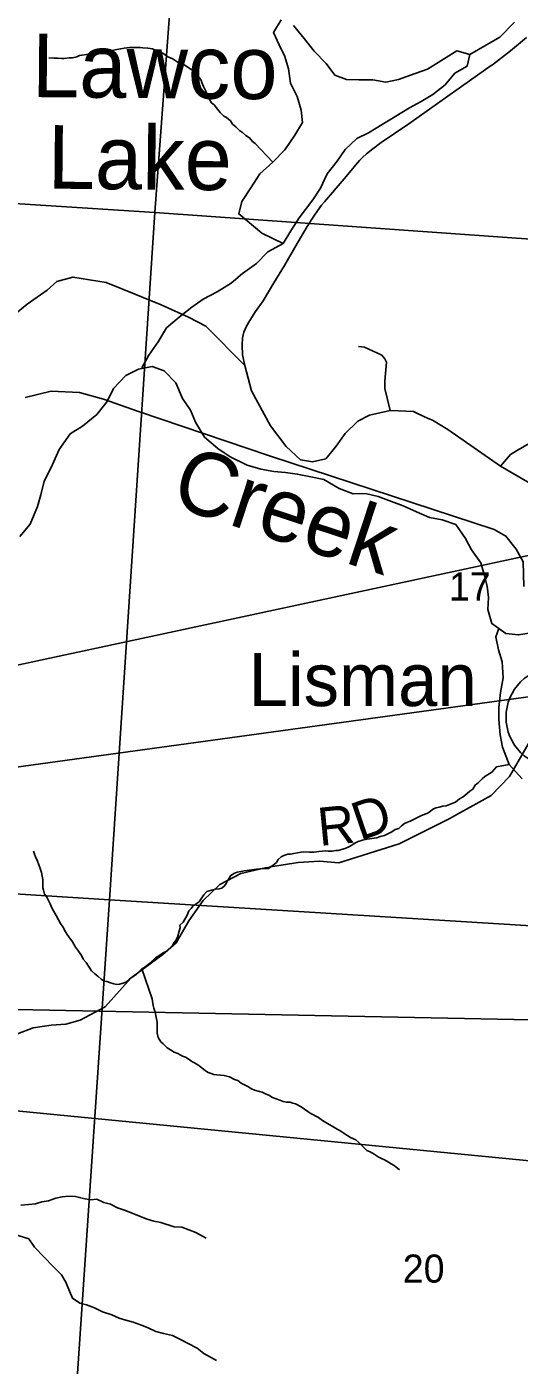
# Model space of a CAD drawing. Extents: x 0 to 44, y -23.8 to 22.
# Drawn here: x 7.321 to 8.055, y 16.706 to 18.701 of the extents above; entities that cross this region are included whole.
import ezdxf

# ---------------------------------------------------------------- set-up
doc = ezdxf.new("R2010")
doc.units = 0
for name, color, linetype in [('GM_X_County_Road', 7, 'Continuous'), ('GM_X_County_Road_Text', 7, 'Continuous'), ('GM_X_Minor_Lake', 7, 'Continuous'), ('GM_X_Minor_Lake_Text', 7, 'Continuous'), ('GM_X_Minor_River', 7, 'Continuous'), ('GM_X_Minor_River_Text', 7, 'Continuous'), ('GM_X_Rail_Line', 7, 'Continuous'), ('GM_X_Section', 7, 'Continuous'), ('GM_X_Section_Text', 7, 'Continuous'), ('GM_X_State_Route', 7, 'Continuous'), ('GM_X_Township_Road', 7, 'Continuous'), ('GM_X_Unincorporated', 7, 'Continuous'), ('GM_X_Unincorporated_Text', 7, 'Continuous'), ('SH_Data', 7, 'Continuous')]:
    doc.layers.add(name, color=color, linetype=linetype)

msp = doc.modelspace()

# ---------------------------------------------------------------- linework, layer by layer
at = {"layer": 'GM_X_County_Road'}
for points in [[(6.9605, 18.0572), (6.9631, 18.0586), (7.0676, 18.0977), (7.1245, 18.1197), (7.1631, 18.1368), (7.1965, 18.1482), (7.2162, 18.1554), (7.226, 18.1596), (7.2355, 18.1759), (7.2488, 18.2089), (7.2601, 18.2305), (7.2791, 18.2525), (7.3219, 18.2874), (7.3518, 18.3079), (7.3662, 18.3212), (7.3901, 18.3277), (7.4398, 18.3193), (7.4838, 18.3016), (7.5032, 18.2938)], [(7.5032, 18.2938), (7.5216, 18.2864), (7.5625, 18.2681), (7.5883, 18.2545), (7.6465, 18.1961)], [(8.0274, 18.0459), (8.0425, 18.0631), (8.0562, 18.0718), (8.0828, 18.0867)], [(7.6845, 17.4488), (7.726, 17.4555), (7.7575, 17.4574), (7.7866, 17.4551), (7.8764, 17.4832), (7.95, 17.5201), (8.0136, 17.5554), (8.0409, 17.5834), (8.0981, 17.6821), (8.1073, 17.6872)], [(7.3076, 17.2002), (7.3307, 17.2091), (7.3578, 17.213), (7.3795, 17.2145), (7.4012, 17.2204), (7.438, 17.2403), (7.477, 17.2835), (7.524, 17.3181), (7.5441, 17.3355), (7.5631, 17.3686), (7.5843, 17.3985), (7.6089, 17.4224), (7.6404, 17.4388), (7.6767, 17.4475), (7.6807, 17.4481), (7.6845, 17.4488)]]:
    msp.add_lwpolyline(points, dxfattribs=at)
at = {"layer": 'GM_X_Minor_Lake'}
for points in [[(7.7007, 18.7107), (7.6893, 18.6918), (7.6975, 18.6736), (7.7058, 18.6561), (7.7117, 18.6378), (7.7146, 18.6165), (7.7244, 18.5968), (7.7304, 18.5762), (7.7325, 18.558), (7.7211, 18.5391), (7.7058, 18.5171), (7.6883, 18.499), (7.6685, 18.4816), (7.6555, 18.4604), (7.6418, 18.44), (7.6372, 18.4218), (7.6719, 18.393), (7.7036, 18.3775)], [(7.8309, 18.5424), (7.8917, 18.58), (7.9092, 18.5891), (7.9267, 18.5996), (7.9449, 18.614), (7.9594, 18.6313), (7.9776, 18.6419), (7.9815, 18.6593), (7.9626, 18.6647), (7.9185, 18.6376), (7.9003, 18.6309), (7.8753, 18.6219), (7.8563, 18.6182), (7.8374, 18.6213), (7.8162, 18.6214), (7.798, 18.6222), (7.7806, 18.6284), (7.7678, 18.6459), (7.7497, 18.6642), (7.7347, 18.6832), (7.7189, 18.7023)], [(7.7036, 18.3775), (7.7151, 18.3964), (7.7273, 18.4161), (7.7479, 18.4425), (7.7593, 18.46), (7.7693, 18.4812), (7.7838, 18.5001), (7.796, 18.5175), (7.8135, 18.5341), (7.8309, 18.5424)]]:
    msp.add_lwpolyline(points, dxfattribs=at)
at = {"layer": 'GM_X_Minor_River'}
for points in [[(8.0484, 18.7072), (8.0263, 18.6853), (7.9815, 18.6593)], [(7.6883, 18.499), (7.6617, 18.5267), (7.658, 18.5294), (7.6535, 18.5352), (7.6478, 18.5387), (7.6426, 18.5433), (7.6388, 18.5456), (7.6332, 18.5514), (7.6279, 18.5556), (7.6249, 18.5602), (7.6193, 18.5656), (7.6152, 18.5676), (7.6095, 18.573), (7.6058, 18.5776), (7.6006, 18.5841), (7.5968, 18.5872), (7.5931, 18.5933), (7.5909, 18.599), (7.5883, 18.6048), (7.5846, 18.6117), (7.5824, 18.6174), (7.5813, 18.6212), (7.5768, 18.627), (7.5745, 18.6308), (7.5693, 18.635), (7.5633, 18.6389), (7.5542, 18.6451), (7.547, 18.6475), (7.538, 18.6533), (7.5316, 18.656), (7.5241, 18.6614), (7.5176, 18.6638), (7.5086, 18.6677), (7.5018, 18.6686), (7.4946, 18.6694), (7.4904, 18.6698), (7.4866, 18.6699), (7.4801, 18.6696), (7.4748, 18.6697), (7.4706, 18.669), (7.4665, 18.6686), (7.4615, 18.6679), (7.4558, 18.6669), (7.4486, 18.665), (7.4433, 18.664), (7.4361, 18.6629), (7.4319, 18.6622), (7.4212, 18.6608), (7.4159, 18.6598), (7.4106, 18.6594), (7.4038, 18.6584), (7.3999, 18.6577), (7.3958, 18.6558), (7.3893, 18.6544), (7.3847, 18.6541), (7.3771, 18.6534), (7.373, 18.6535), (7.3677, 18.6539), (7.3616, 18.654), (7.3544, 18.6545)], [(7.7036, 18.3775), (7.6809, 18.3651), (7.6637, 18.3477), (7.6431, 18.333), (7.626, 18.3187), (7.6054, 18.3058), (7.5845, 18.2946), (7.5673, 18.2829), (7.5487, 18.2678), (7.5296, 18.2519), (7.5173, 18.2311), (7.5035, 18.2111), (7.4935, 18.1936), (7.4931, 18.1916)], [(8.0075, 17.8671), (8.0031, 17.8843), (7.9979, 17.9018), (7.9844, 17.9212), (7.9754, 17.9383), (7.9607, 17.9589), (7.9407, 17.9658), (7.9217, 17.9693), (7.9021, 17.9778), (7.8824, 17.987), (7.865, 17.9932), (7.8449, 18.0009), (7.8264, 18.0051), (7.8078, 18.0049), (7.787, 18.0126), (7.764, 18.026), (7.7446, 18.0302), (7.7246, 18.0341), (7.7071, 18.0365), (7.6897, 18.0377), (7.6704, 18.0412), (7.65, 18.0474), (7.6246, 18.0597), (7.6061, 18.0723), (7.5865, 18.0891), (7.573, 18.1116), (7.5652, 18.1291), (7.5535, 18.1466), (7.5434, 18.1702), (7.5261, 18.1878), (7.5083, 18.1943), (7.4878, 18.1906), (7.4688, 18.1812), (7.4505, 18.1616), (7.4413, 18.1423), (7.4256, 18.123), (7.4046, 18.1056), (7.3859, 18.0939), (7.3695, 18.0705), (7.3575, 18.044), (7.3472, 18.0235), (7.3421, 18.003), (7.3374, 17.986), (7.3263, 17.9595), (7.311, 17.9413)], [(8.073, 17.7977), (8.0544, 17.7944), (8.0355, 17.7964), (8.0147, 17.8113), (8.0088, 17.8322), (8.0097, 17.8501), (8.0075, 17.8671)], [(8.0598, 17.5798), (8.0406, 17.6016), (8.0305, 17.6271), (8.0269, 17.6457), (8.0248, 17.6685), (8.0249, 17.6863), (8.0273, 17.7087), (8.0316, 17.7307), (8.0299, 17.7543), (8.0247, 17.7721), (8.0207, 17.7915), (8.0249, 17.804)], [(8.0406, 17.6016), (8.0213, 17.5978), (8.0144, 17.5899), (8.0041, 17.5836), (7.9999, 17.5802), (7.9945, 17.5746), (7.9899, 17.5708), (7.986, 17.5648), (7.9818, 17.5618), (7.978, 17.5581), (7.9719, 17.5532), (7.9665, 17.5502), (7.9604, 17.5454), (7.9539, 17.5428), (7.9463, 17.5399), (7.9417, 17.5392), (7.936, 17.5377), (7.9314, 17.537), (7.9276, 17.5352), (7.9192, 17.5288), (7.9146, 17.5273), (7.9089, 17.5248), (7.9009, 17.5211), (7.8937, 17.5173), (7.8845, 17.5133), (7.8799, 17.5099), (7.8757, 17.5062), (7.8704, 17.5047), (7.8654, 17.501), (7.8547, 17.4958), (7.8479, 17.494), (7.8433, 17.4921), (7.8391, 17.4918), (7.8323, 17.4908), (7.8281, 17.49), (7.822, 17.4886), (7.8155, 17.4868), (7.8113, 17.4846), (7.8022, 17.4794), (7.7961, 17.4764), (7.7904, 17.4749), (7.7854, 17.4731), (7.7816, 17.4732), (7.7767, 17.4725), (7.7706, 17.4725), (7.7664, 17.4726), (7.7565, 17.4716), (7.7497, 17.4709), (7.7429, 17.471), (7.7345, 17.4715), (7.7304, 17.4708), (7.7247, 17.4697), (7.7193, 17.469), (7.7144, 17.4679), (7.7106, 17.4676), (7.7045, 17.4658), (7.7003, 17.4639), (7.6961, 17.4598), (7.6934, 17.4556), (7.6888, 17.4515), (7.6819, 17.4463), (7.6766, 17.4463), (7.6686, 17.4461), (7.6637, 17.4454), (7.6568, 17.4443), (7.6527, 17.444), (7.6454, 17.4429), (7.6405, 17.4419), (7.6352, 17.4408), (7.6302, 17.4389), (7.6249, 17.4356), (7.6229, 17.4318), (7.6206, 17.4281), (7.6187, 17.4243), (7.6163, 17.4205), (7.6121, 17.4171), (7.6083, 17.416), (7.6026, 17.4154), (7.5969, 17.4139), (7.5897, 17.4121), (7.5855, 17.4072), (7.5785, 17.397), (7.5693, 17.3907), (7.5666, 17.3869), (7.5628, 17.3832), (7.5604, 17.3771), (7.5546, 17.3666), (7.5497, 17.3621), (7.55, 17.3579), (7.5484, 17.353), (7.5464, 17.3454), (7.5445, 17.3405), (7.541, 17.3363), (7.5379, 17.3307), (7.5299, 17.3232), (7.5249, 17.321), (7.5184, 17.3165), (7.5134, 17.3135), (7.5046, 17.3053), (7.4969, 17.2989), (7.4931, 17.297)], [(7.4931, 17.297), (7.4851, 17.2892), (7.4793, 17.2851), (7.4747, 17.2821), (7.469, 17.2772), (7.4652, 17.2757), (7.4595, 17.2739), (7.4557, 17.2736), (7.4511, 17.2748), (7.4447, 17.2768), (7.4409, 17.2779), (7.4371, 17.2788), (7.4322, 17.2815), (7.4274, 17.2861), (7.4229, 17.2896), (7.418, 17.2938), (7.4146, 17.2992), (7.4101, 17.3064), (7.4056, 17.3111), (7.4027, 17.3168), (7.3986, 17.3233), (7.3941, 17.3291), (7.3896, 17.3371), (7.384, 17.3444), (7.3814, 17.3482), (7.3792, 17.352), (7.3751, 17.3593), (7.3717, 17.3643), (7.3688, 17.3697), (7.3654, 17.3762), (7.361, 17.3834), (7.358, 17.3888), (7.3561, 17.3938), (7.3513, 17.4037), (7.348, 17.4083), (7.3465, 17.414), (7.3454, 17.4178), (7.3451, 17.4247), (7.3452, 17.43), (7.3445, 17.4349), (7.3434, 17.4406), (7.3412, 17.4464), (7.339, 17.4532), (7.3372, 17.4574), (7.3346, 17.4639), (7.3331, 17.4677), (7.3316, 17.4723)], [(7.4931, 17.297), (7.5082, 17.2524), (7.5089, 17.2486), (7.51, 17.2425), (7.511, 17.2383), (7.5125, 17.2326), (7.5143, 17.225), (7.5157, 17.2177), (7.5157, 17.2124), (7.5156, 17.2075), (7.5159, 17.201), (7.5174, 17.1945), (7.5211, 17.1884), (7.5248, 17.1853), (7.5308, 17.1792), (7.5357, 17.1761), (7.541, 17.1726), (7.5463, 17.1706), (7.5535, 17.1667), (7.558, 17.1652), (7.5633, 17.1617), (7.5674, 17.159), (7.5716, 17.157), (7.5761, 17.1539), (7.5825, 17.1493), (7.5877, 17.145), (7.5915, 17.1427), (7.5964, 17.1411), (7.6002, 17.1395), (7.6047, 17.1391), (7.6154, 17.1382), (7.6233, 17.1358), (7.6308, 17.1319), (7.6358, 17.1307), (7.641, 17.1265), (7.6508, 17.1214), (7.6565, 17.118), (7.6606, 17.1164), (7.6682, 17.114), (7.672, 17.1132), (7.678, 17.1101), (7.6822, 17.1089), (7.6874, 17.1054), (7.6931, 17.1034), (7.6988, 17.1011), (7.7037, 17.0991), (7.7079, 17.0983), (7.7139, 17.0982), (7.7177, 17.0967), (7.7219, 17.0959), (7.726, 17.0939), (7.7317, 17.0904), (7.7437, 17.0819), (7.7561, 17.0753), (7.7622, 17.071), (7.772, 17.0652), (7.7765, 17.0625), (7.784, 17.0578), (7.7882, 17.0563), (7.7946, 17.0516), (7.804, 17.0458), (7.8119, 17.0423), (7.8164, 17.0384), (7.8284, 17.0261), (7.833, 17.0242), (7.839, 17.0207), (7.845, 17.0168), (7.8499, 17.0141), (7.8548, 17.0125), (7.8605, 17.009), (7.8646, 17.0063), (7.8691, 17.004), (7.8767, 16.9974)], [(7.3123, 16.945), (7.3241, 16.946), (7.3343, 16.9467), (7.3438, 16.9497), (7.3537, 16.9515), (7.3647, 16.9552), (7.3742, 16.9571), (7.3836, 16.9581), (7.3942, 16.9577), (7.406, 16.9546), (7.4162, 16.953), (7.426, 16.9537), (7.4362, 16.9487), (7.4464, 16.9463), (7.4566, 16.941), (7.4683, 16.9371), (7.4797, 16.9325), (7.5008, 16.924), (7.511, 16.9212), (7.5212, 16.9189), (7.5409, 16.9127), (7.5526, 16.9119), (7.5628, 16.908), (7.5734, 16.9041), (7.5832, 16.8988), (7.5889, 16.8957)], [(7.3037, 16.901), (7.3242, 16.8944), (7.3328, 16.8823), (7.3472, 16.8674), (7.3604, 16.8537), (7.3729, 16.8412), (7.3796, 16.8301), (7.3849, 16.8168), (7.3894, 16.8062), (7.4004, 16.799), (7.4102, 16.7963), (7.4223, 16.7917), (7.4344, 16.786), (7.448, 16.7814), (7.459, 16.7764), (7.4692, 16.7737), (7.4798, 16.7706), (7.4907, 16.7664), (7.5021, 16.7618), (7.5138, 16.7565), (7.5252, 16.7534), (7.5388, 16.7507), (7.5497, 16.7454), (7.5618, 16.7389), (7.5751, 16.7316), (7.5853, 16.7236), (7.5951, 16.7183), (7.6042, 16.7133)]]:
    msp.add_lwpolyline(points, dxfattribs=at)
at = {"layer": 'GM_X_Rail_Line'}
msp.add_lwpolyline([(8.0624, 17.8667), (8.061, 17.9033), (8.051, 17.922), (8.0356, 17.9418), (8.0181, 17.9517), (7.6833, 18.0613), (7.4877, 18.1275), (7.4357, 18.1458), (7.4001, 18.1557), (7.3576, 18.1574), (7.3191, 18.1482)], dxfattribs=at)
at = {"layer": 'GM_X_Section'}
for points in [[(6.5821, 19.5069), (7.5875, 19.4351), (7.5123, 18.4238), (6.5134, 18.488)], [(7.5875, 19.4351), (8.6049, 19.3603), (8.5278, 18.3516), (7.5123, 18.4238)], [(6.5134, 18.488), (7.5123, 18.4238), (7.4446, 17.3999), (6.4419, 17.4633)], [(7.5123, 18.4238), (8.5278, 18.3516), (8.4522, 17.3376), (7.4446, 17.3999)], [(6.4419, 17.4633), (7.4446, 17.3999), (7.376, 16.3855), (6.3745, 16.447)], [(7.4446, 17.3999), (8.4522, 17.3376), (8.3848, 16.3266), (7.376, 16.3855)]]:
    msp.add_lwpolyline(points, close=True, dxfattribs=at)
at = {"layer": 'GM_X_State_Route'}
for points in [[(8.066, 18.6846), (8.0422, 18.6645), (8.0154, 18.6441), (8.0137, 18.643), (8.0052, 18.6367), (7.9694, 18.6114), (7.9526, 18.5997), (7.9214, 18.5776), (7.8908, 18.5559), (7.8496, 18.528), (7.8371, 18.5188), (7.8275, 18.511), (7.822, 18.506), (7.8171, 18.5011), (7.8112, 18.4946), (7.8049, 18.4866), (7.7945, 18.474), (7.7653, 18.4396), (7.7607, 18.4346), (7.7512, 18.4216), (7.7463, 18.414), (7.7392, 18.4028), (7.7211, 18.3719), (7.7053, 18.3448), (7.6895, 18.3189), (7.6739, 18.2922), (7.6623, 18.2762), (7.6538, 18.2627), (7.6489, 18.2543), (7.6447, 18.2454), (7.643, 18.2372), (7.6422, 18.2261), (7.643, 18.2117), (7.6465, 18.1961), (7.6564, 18.158), (7.6846, 18.1058), (7.7078, 18.0752), (7.7295, 18.0552), (7.7473, 18.0524), (7.7671, 18.0568), (7.7824, 18.0756), (7.7959, 18.0944), (7.8146, 18.1128), (7.8321, 18.1221), (7.8628, 18.1288), (7.8636, 18.129), (7.8977, 18.1271), (7.9039, 18.1243), (7.9198, 18.1171)], [(7.9198, 18.1171), (7.926, 18.1143), (7.9489, 18.1004), (8.0274, 18.0459), (8.1481, 17.9761)]]:
    msp.add_lwpolyline(points, dxfattribs=at)
at = {"layer": 'GM_X_Township_Road'}
msp.add_lwpolyline([(7.8628, 18.1288), (7.8552, 18.1615), (7.855, 18.1727), (7.8574, 18.2006), (7.8552, 18.2056), (7.8504, 18.2112), (7.8248, 18.2231), (7.8156, 18.2244)], dxfattribs=at)
at = {"layer": 'GM_X_Unincorporated'}
msp.add_circle((8.1101, 17.6719), 0.0744, dxfattribs=at)
at = {"layer": 'SH_Data'}
for points in [[(5.3413, 17.3275), (9.7799, 18.2797), (9.7799, 17.9369)], [(5.3505, 17.2755), (9.7548, 17.1872), (9.7548, 16.8468)]]:
    msp.add_lwpolyline(points, close=True, dxfattribs=at)

# ---------------------------------------------------------------- texts
at = {"layer": 'GM_X_County_Road_Text'}
for s, rotation, p in [('D', 18.8699, (7.818, 17.4875)), ('R', 5.5762, (7.7577, 17.4799))]:
    msp.add_text(s, height=0.0568, rotation=rotation, dxfattribs=at).set_placement(p)
at = {"layer": 'GM_X_Minor_Lake_Text'}
for s, rotation, p in [('Lawco', 359.4987, (7.3288, 18.5958)), ('Lake', 359.4988, (7.3522, 18.4594))]:
    msp.add_text(s, height=0.0947, rotation=rotation, dxfattribs=at).set_placement(p)
at = {"layer": 'GM_X_Minor_River_Text'}
msp.add_text('Creek', height=0.09469, rotation=341.8119, dxfattribs=at).set_placement((7.5328, 17.9883))
at = {"layer": 'GM_X_Section_Text'}
for s, p in [('17', (7.9506, 17.8457)), ('20', (7.8818, 16.8294))]:
    msp.add_text(s, height=0.04186, rotation=0, dxfattribs=at).set_placement(p)
at = {"layer": 'GM_X_Unincorporated_Text'}
msp.add_text('Lisman', height=0.07898, rotation=0, dxfattribs=at).set_placement((7.6518, 17.6884))

doc.saveas('drawing.dxf')
